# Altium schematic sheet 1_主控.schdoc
size 497 x 243 mm
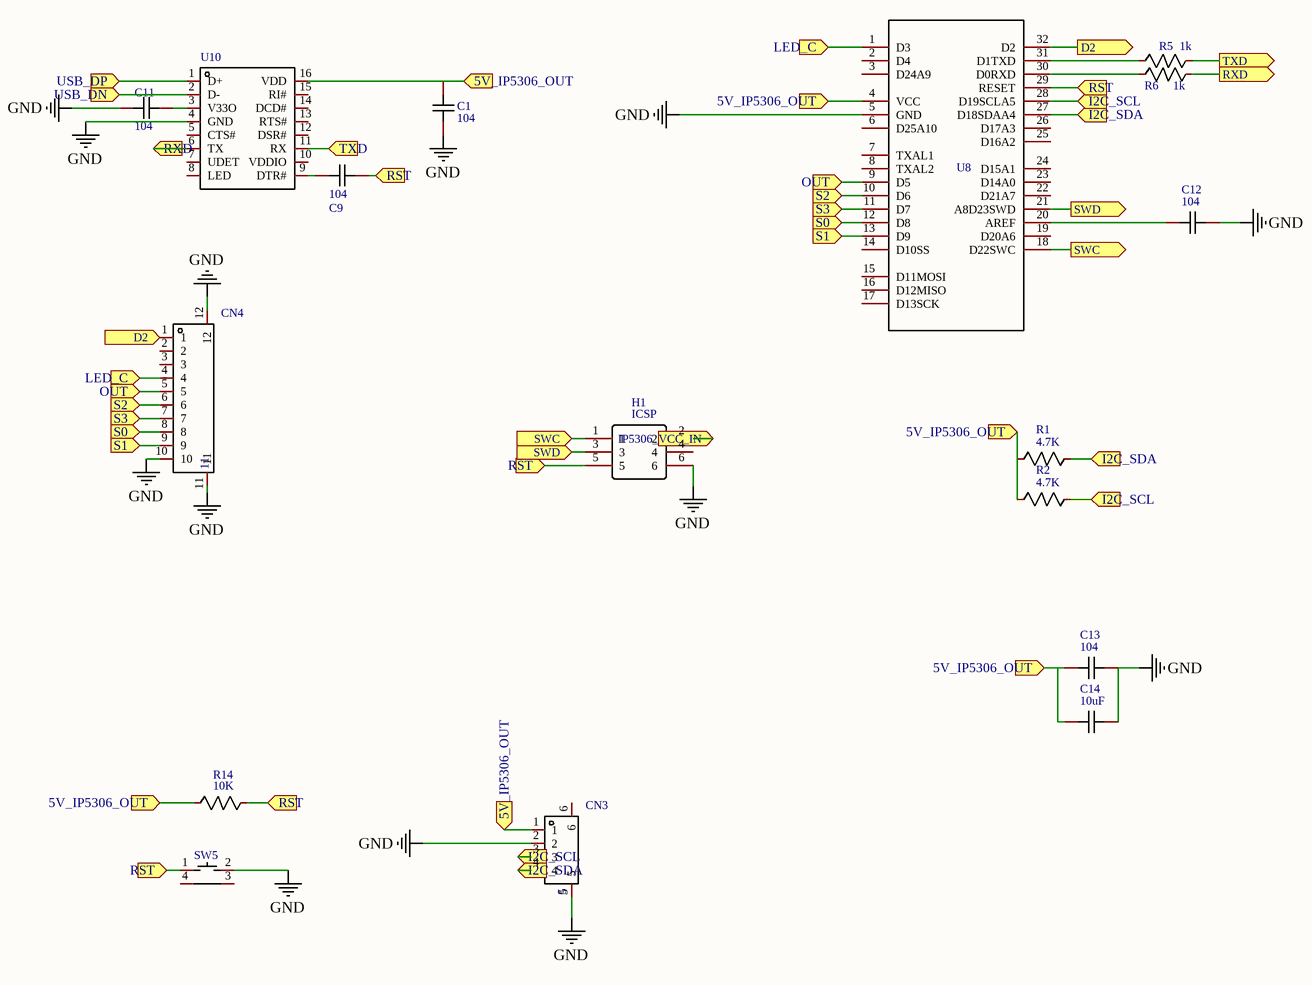
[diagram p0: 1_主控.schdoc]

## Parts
C1  104  [C0805]
C9  104  [C0805]
C11  104  [C0805]
C12  104  [C0805]
C13  104  [C0805]
C14  10uF  [C0805]
CN3  NUMBER: 5  [CONN-SMD_4P-P2.00_HDGC_HDGC2001WR-S-4P]  (hidden comment: HDGC2001WR-S-4P)
CN4  NAME: 11  [CONN-TH_10P-P2.00_XUNPU_WAFER-PH2.0-10PWB]  (hidden comment: WAFER-PH2.0-10PWB)
H1  Name: ICSP  (hidden comment: A2541WV-2x3P)
R1  4.7K
R2  4.7K
R5  1k  [R0805_NEW]
R6  1k  [R0805_NEW]
R14  10K
SW5  KH-6X6X6H-ZJ  [SW-TH_KH-6X6X6H-ZJ-A]  (value not drawn)
U8  LGT8F328P  [LGT328 TQFP-32_]  (value not drawn)
U10  HT42B534-2  [NSOP-16_L9.9-W3.9-P1.27-LS6.0-BL]  (value not drawn)

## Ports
5V_IP5306_OUT (in), D2 (in), D2 (out), I2C_SCL (in), I2C_SDA (in), IP5306_VCC_IN (in), LED_C (in), OUT (in), RST (in), RXD (in), RXD (out), S0 (in), S1 (in), S2 (in), S3 (in), SWC (in), SWC (out), SWD (in), SWD (out), TXD (in), TXD (out), USB_DN (in), USB_DP (in)

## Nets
GND: C1.1 C11.2 C12.1 C13.1 C14.1 CN3.2 CN3.5 CN4.10 CN4.11 CN4.12 H1.6 SW5.2 U8.5(GND) U10.4(GND)
5V_IP5306_OUT: C1.2 C13.2 C14.2 CN3.1 R1.2 R2.2 R14.1 U8.4(VCC) U10.16(VDD) ; port 5V_IP5306_OUT
D2: CN4.1 U8.32(D2) ; port D2
I2C_SCL: CN3.3 R2.1 U8.28(D19SCLA5) ; port I2C_SCL
I2C_SDA: CN3.4 R1.1 U8.27(D18SDAA4) ; port I2C_SDA
IP5306_VCC_IN: H1.2 ; port IP5306_VCC_IN
LED_C: CN4.4 U8.1(D3) ; port LED_C
OUT: CN4.5 U8.9(D5) ; port OUT
RST: C9.2 H1.5 R14.2 SW5.1 U8.29(RESET) ; port RST
RXD: R6.2 U10.6(TX) ; port RXD
S0: CN4.8 U8.12(D8) ; port S0
S1: CN4.9 U8.13(D9) ; port S1
S2: CN4.6 U8.10(D6) ; port S2
S3: CN4.7 U8.11(D7) ; port S3
SWC: H1.1 U8.18(D22SWC) ; port SWC
SWD: H1.3 U8.21(A8D23SWD) ; port SWD
TXD: R5.2 U10.11(RX) ; port TXD
USB_DN: U10.2(D-) ; port USB_DN
USB_DP: U10.1(D+) ; port USB_DP
NetC9_1: C9.1 U10.9(DTR#)
NetC11_1: C11.1 U10.3(V33O)
NetC12_2: C12.2 U8.20(AREF)
NetR5_1: R5.1 U8.31(D1TXD)
NetR6_1: R6.1 U8.30(D0RXD)

Not connected (* = marked no-connect by the designer): CN3 6; CN4 2 3; H1 4; SW5 3 4; U8 2(D4) 3(D24A9) 6(D25A10) 7(TXAL1) 8(TXAL2) 14(D10SS) 15(D11MOSI) 16(D12MISO) 17(D13SCK) 19(D20A6) 22(D21A7) 23(D14A0) 24(D15A1) 25(D16A2) 26(D17A3); U10 5(CTS#) 7(UDET) 8(LED) 10(VDDIO) 12(DSR#) 13(RTS#) 14(DCD#) 15(RI#)

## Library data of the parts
C1 C9 C12 C13 = 104: Convert to PCB: yes; Origin Footprint: C0603
C11 = 104: Convert to PCB: yes; Origin Footprint: C0603; NUMBER: 2
C14 = 10uF: Convert to PCB: yes; Origin Footprint: C0603
CN3 = HDGC2001WR-S-4P: 参考系列:PH;间距:2mm;插针结构:1x4P;排数:1;每排PIN数:4;行距:-;公母:公型插针;安装方式:卧贴;额定电流:5A;工作温度范围:-25~+70;; Manufacturer: HDGC(华德共创); Add into BOM: yes; Reference Series: PH; Pitch: 2mm; Pins Structure: 1x4P; Number of PINs Per Row: 4; Gender: 公型插针; Current Rating (Max): 5A
CN4 = WAFER-PH2.0-10PWB: Manufacturer: XUNPU(讯普); Add into BOM: yes
H1 = A2541WV-2x3P: Manufacturer: Changjiang Connectors; Convert to PCB: yes; Origin Footprint: HDR-TH_6P-P2.54-V-R2-C3-S2.54_A2541WV-2X3P
R1 R2 = 4.7K: Convert to PCB: yes; Origin Footprint: R0805
R5 R6 = 1k: Convert to PCB: yes; Origin Footprint: R0805
R14 = 10K: Convert to PCB: yes; Origin Footprint: R0603
SW5 = KH-6X6X6H-ZJ: 绝缘电阻:100MΩ;电路结构:单刀单掷;安装方式:卧插;按钮形状:圆形按钮;按钮/盖帽颜色:黑色;机械寿命:100000;引脚样式:PC引脚;开关长度:6mm;开关宽度:6mm;开关高度:6mm;带支架:是;; Manufacturer: kinghelm(金航标); Add into BOM: yes; Insulation Resistance: 100MΩ; Circuit: 单刀单掷; Actuator Style: 圆形按钮; Actuator/Cap Color: 黑色; Mechanical Life: 100000; Pin Style: PC引脚; Switch Length: 6mm; Strike Gundam: 是
U8 = LGT8F328P: Add into BOM: yes
U10 = HT42B534-2: 类型:-;协议类别:-;驱动器/接收器数:-;数据速率:-;; Manufacturer: HOLTEK(台湾合泰/盛群); Symbol: HT42B534-2_C493361; Add into BOM: yes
